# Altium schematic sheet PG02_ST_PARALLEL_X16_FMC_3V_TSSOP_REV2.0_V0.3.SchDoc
size 419 x 241 mm
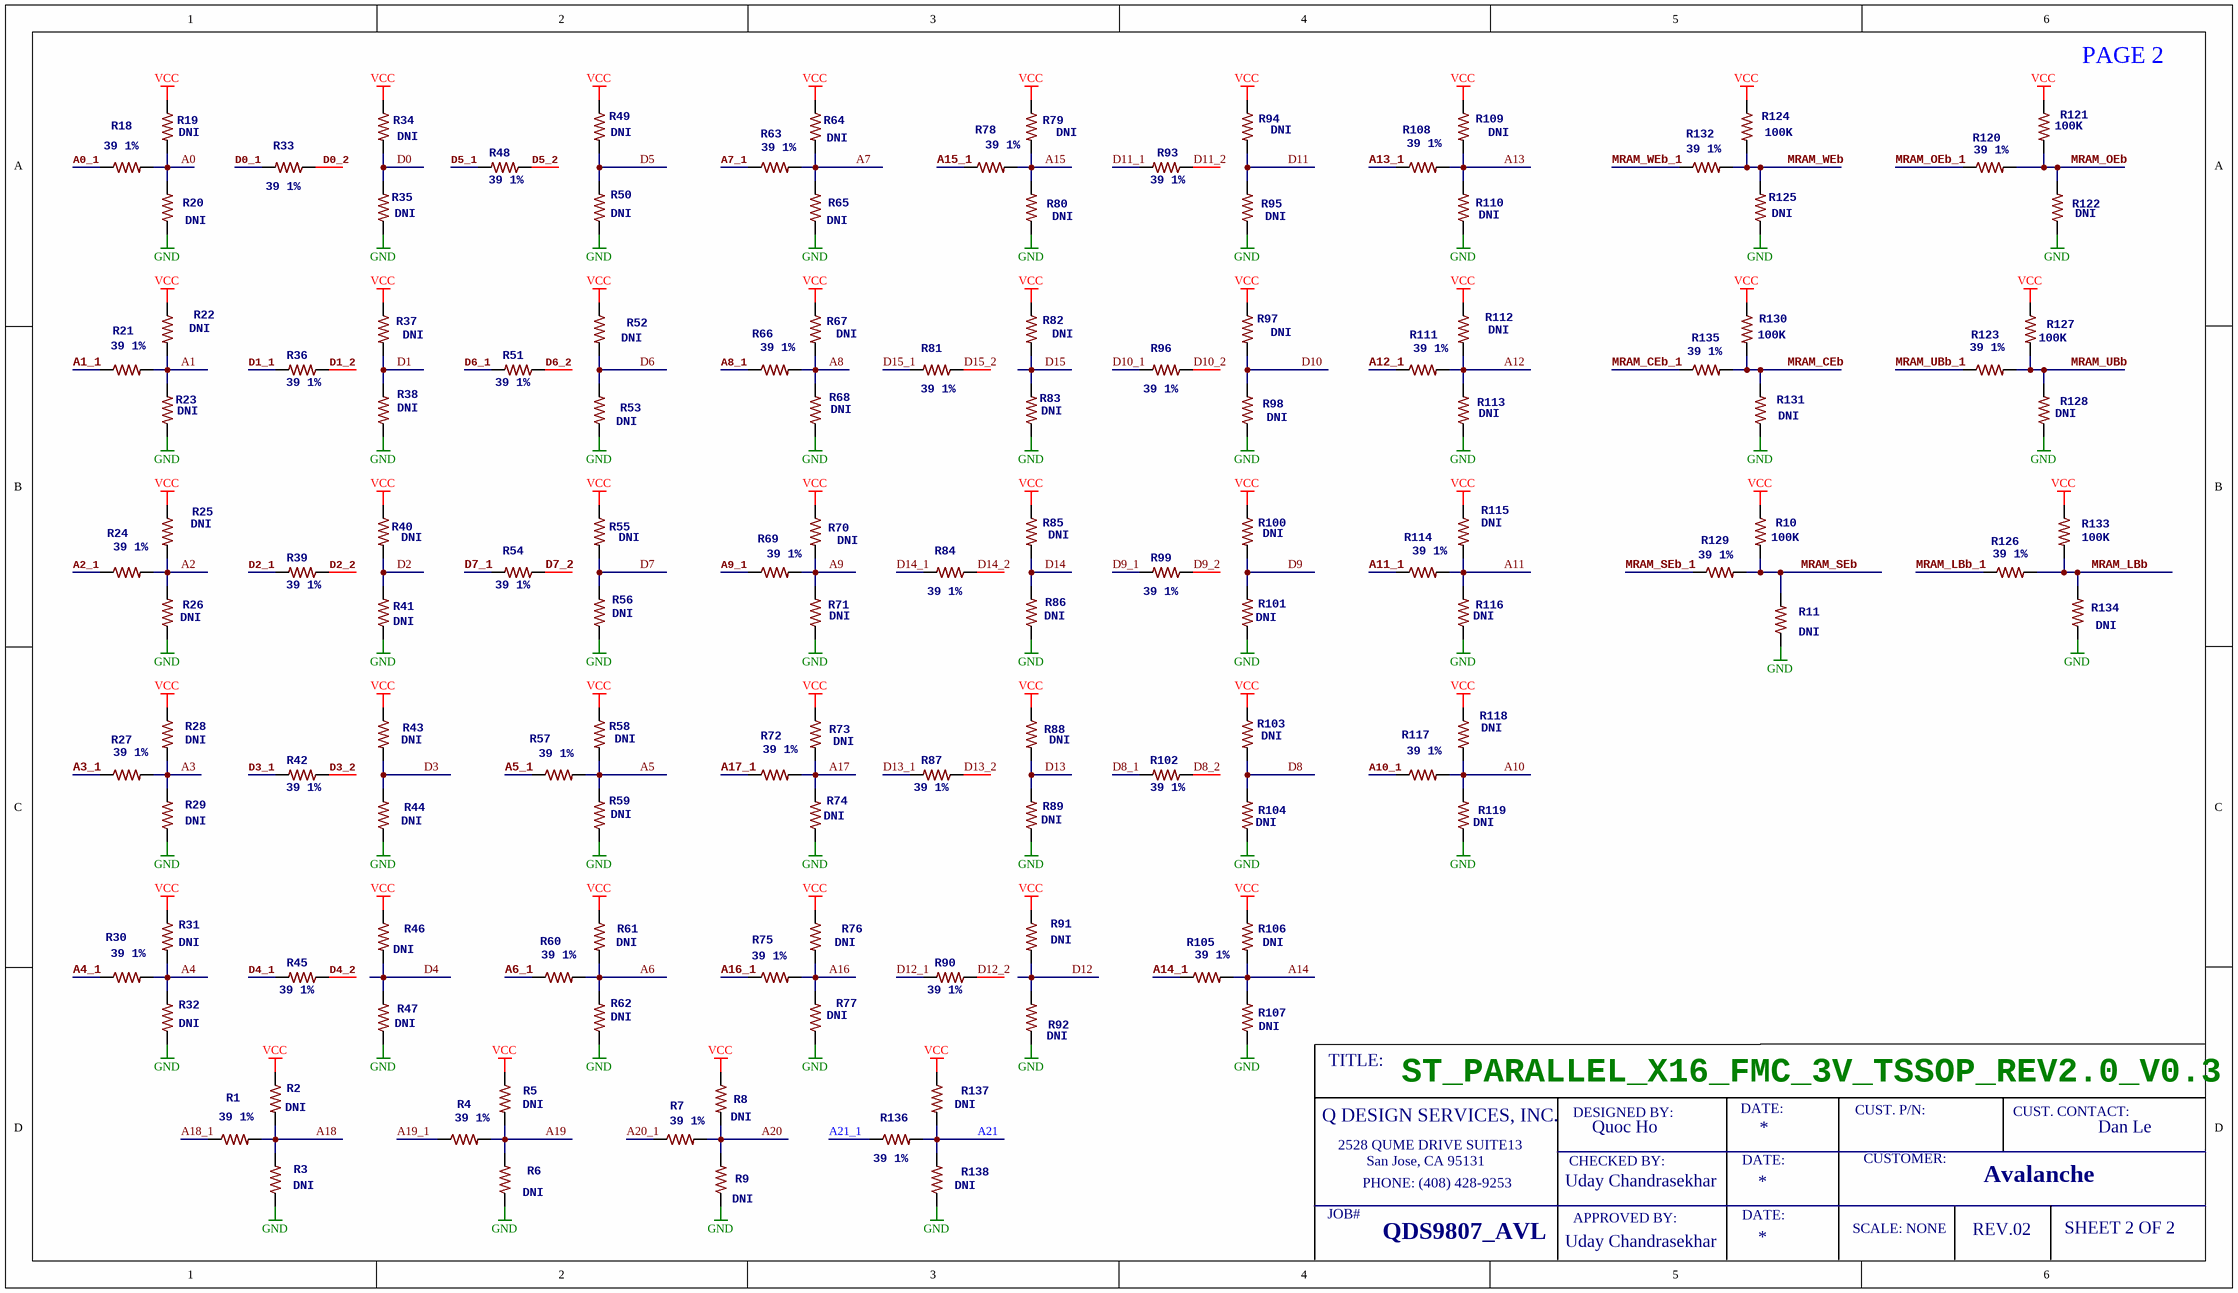
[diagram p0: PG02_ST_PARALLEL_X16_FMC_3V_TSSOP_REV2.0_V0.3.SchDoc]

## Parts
R1  39 1%  [N_0603]
R2  DNI  [N_0402]
R3  DNI  [N_0402]
R4  39 1%  [N_0603]
R5  DNI  [N_0402]
R6  DNI  [N_0402]
R7  39 1%  [N_0603]
R8  DNI  [N_0402]
R9  DNI  [N_0402]
R10  100K  [N_0402]
R11  DNI  [N_0402]
R18  39 1%  [N_0603]
R19  DNI  [N_0402]
R20  DNI  [N_0402]
R21  39 1%  [N_0603]
R22  DNI  [N_0402]
R23  DNI  [N_0402]
R24  39 1%  [N_0603]
R25  DNI  [N_0402]
R26  DNI  [N_0402]
R27  39 1%  [N_0603]
R28  DNI  [N_0402]
R29  DNI  [N_0402]
R30  39 1%  [N_0603]
R31  DNI  [N_0402]
R32  DNI  [N_0402]
R33  39 1%  [N_0603]
R34  DNI  [N_0402]
R35  DNI  [N_0402]
R36  39 1%  [N_0603]
R37  DNI  [N_0402]
R38  DNI  [N_0402]
R39  39 1%  [N_0603]
R40  DNI  [N_0402]
R41  DNI  [N_0402]
R42  39 1%  [N_0603]
R43  DNI  [N_0402]
R44  DNI  [N_0402]
R45  39 1%  [N_0603]
R46  DNI  [N_0402]
R47  DNI  [N_0402]
R48  39 1%  [N_0603]
R49  DNI  [N_0402]
R50  DNI  [N_0402]
R51  39 1%  [N_0603]
R52  DNI  [N_0402]
R53  DNI  [N_0402]
R54  39 1%  [N_0603]
R55  DNI  [N_0402]
R56  DNI  [N_0402]
R57  39 1%  [N_0603]
R58  DNI  [N_0402]
R59  DNI  [N_0402]
R60  39 1%  [N_0603]
R61  DNI  [N_0402]
R62  DNI  [N_0402]
R63  39 1%  [N_0603]
R64  DNI  [N_0402]
R65  DNI  [N_0402]
R66  39 1%  [N_0603]
R67  DNI  [N_0402]
R68  DNI  [N_0402]
R69  39 1%  [N_0603]
R70  DNI  [N_0402]
R71  DNI  [N_0402]
R72  39 1%  [N_0603]
R73  DNI  [N_0402]
R74  DNI  [N_0402]
R75  39 1%  [N_0603]
R76  DNI  [N_0402]
R77  DNI  [N_0402]
R78  39 1%  [N_0603]
R79  DNI  [N_0402]
R80  DNI  [N_0402]
R81  39 1%  [N_0603]
R82  DNI  [N_0402]
R83  DNI  [N_0402]
R84  39 1%  [N_0603]
R85  DNI  [N_0402]
R86  DNI  [N_0402]
R87  39 1%  [N_0603]
R88  DNI  [N_0402]
R89  DNI  [N_0402]
R90  39 1%  [N_0603]
R91  DNI  [N_0402]
R92  DNI  [N_0402]
R93  39 1%  [N_0603]
R94  DNI  [N_0402]
R95  DNI  [N_0402]
R96  39 1%  [N_0603]
R97  DNI  [N_0402]
R98  DNI  [N_0402]
R99  39 1%  [N_0603]
R100  DNI  [N_0402]
R101  DNI  [N_0402]
R102  39 1%  [N_0603]
R103  DNI  [N_0402]
R104  DNI  [N_0402]
R105  39 1%  [N_0603]
R106  DNI  [N_0402]
R107  DNI  [N_0402]
R108  39 1%  [N_0603]
R109  DNI  [N_0402]
R110  DNI  [N_0402]
R111  39 1%  [N_0603]
R112  DNI  [N_0402]
R113  DNI  [N_0402]
R114  39 1%  [N_0603]
R115  DNI  [N_0402]
R116  DNI  [N_0402]
R117  39 1%  [N_0603]
R118  DNI  [N_0402]
R119  DNI  [N_0402]
R120  39 1%  [N_0603]
R121  100K  [N_0402]
R122  DNI  [N_0402]
R123  39 1%  [N_0603]
R124  100K  [N_0402]
R125  DNI  [N_0402]
R126  39 1%  [N_0603]
R127  100K  [N_0402]
R128  DNI  [N_0402]
R129  39 1%  [N_0603]
R130  100K  [N_0402]
R131  DNI  [N_0402]
R132  39 1%  [N_0603]
R133  100K  [N_0402]
R134  DNI  [N_0402]
R135  39 1%  [N_0603]
R136  39 1%  [N_0603]
R137  DNI  [N_0402]
R138  DNI  [N_0402]

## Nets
GND: R3.1 R6.1 R9.1 R11.1 R20.1 R23.1 R26.1 R29.1 R32.1 R35.1 R38.1 R41.1 R44.1 R47.1 R50.1 R53.1 R56.1 R59.1 R62.1 R65.1 R68.1 R71.1 R74.1 R77.1 R80.1 R83.1 R86.1 R89.1 R92.1 R95.1 R98.1 R101.1 R104.1 R107.1 R110.1 R113.1 R116.1 R119.1 R122.1 R125.1 R128.1 R131.1 R134.1 R138.1
VCC: R2.1 R5.1 R8.1 R10.1 R19.1 R22.1 R25.1 R28.1 R31.1 R34.1 R37.1 R40.1 R43.1 R46.1 R49.1 R52.1 R55.1 R58.1 R61.1 R64.1 R67.1 R70.1 R73.1 R76.1 R79.1 R82.1 R85.1 R88.1 R91.1 R94.1 R97.1 R100.1 R103.1 R106.1 R109.1 R112.1 R115.1 R118.1 R121.1 R124.1 R127.1 R130.1 R133.1 R137.1
A0: R18.2 R19.2 R20.2
A0_1: R18.1
A1: R21.1 R22.2 R23.2
A1_1: R21.2
A2: R24.1 R25.2 R26.2
A2_1: R24.2
A3: R27.1 R28.2 R29.2
A3_1: R27.2
A4: R30.1 R31.2 R32.2
A4_1: R30.2
A5: R57.1 R58.2 R59.2
A5_1: R57.2
A6: R60.1 R61.2 R62.2
A6_1: R60.2
A7: R63.1 R64.2 R65.2
A7_1: R63.2
A8: R66.1 R67.2 R68.2
A8_1: R66.2
A9: R69.1 R70.2 R71.2
A9_1: R69.2
A10: R117.1 R118.2 R119.2
A10_1: R117.2
A11: R114.1 R115.2 R116.2
A11_1: R114.2
A12: R111.1 R112.2 R113.2
A12_1: R111.2
A13: R108.1 R109.2 R110.2
A13_1: R108.2
A14: R105.1 R106.2 R107.2
A14_1: R105.2
A15: R78.1 R79.2 R80.2
A15_1: R78.2
A16: R75.1 R76.2 R77.2
A16_1: R75.2
A17: R72.1 R73.2 R74.2
A17_1: R72.2
A18: R1.1 R2.2 R3.2
A18_1: R1.2
A19: R4.1 R5.2 R6.2
A19_1: R4.2
A20: R7.1 R8.2 R9.2
A20_1: R7.2
A21: R136.1 R137.2 R138.2
A21_1: R136.2
D0: R34.2 R35.2
D0_1: R33.1
D0_2: R33.2
D1: R37.2 R38.2
D1_1: R36.1
D1_2: R36.2
D2: R40.2 R41.2
D2_1: R39.1
D2_2: R39.2
D3: R43.2 R44.2
D3_1: R42.2
D3_2: R42.1
D4: R46.2 R47.2
D4_1: R45.1
D4_2: R45.2
D5: R49.2 R50.2
D5_1: R48.1
D5_2: R48.2
D6: R52.2 R53.2
D6_1: R51.1
D6_2: R51.2
D7: R55.2 R56.2
D7_1: R54.1
D7_2: R54.2
D8: R103.2 R104.2
D8_1: R102.1
D8_2: R102.2
D9: R100.2 R101.2
D9_1: R99.1
D9_2: R99.2
D10: R97.2 R98.2
D10_1: R96.1
D10_2: R96.2
D11: R94.2 R95.2
D11_1: R93.1
D11_2: R93.2
D12: R91.2 R92.2
D12_1: R90.1
D12_2: R90.2
D13: R88.2 R89.2
D13_1: R87.1
D13_2: R87.2
D14: R85.2 R86.2
D14_1: R84.1
D14_2: R84.2
D15: R82.2 R83.2
D15_1: R81.1
D15_2: R81.2
MRAM_CEb: R130.2 R131.2 R135.1
MRAM_CEb_1: R135.2
MRAM_LBb: R126.1 R133.2 R134.2
MRAM_LBb_1: R126.2
MRAM_OEb: R120.1 R121.2 R122.2
MRAM_OEb_1: R120.2
MRAM_SEb: R10.2 R11.2 R129.1
MRAM_SEb_1: R129.2
MRAM_UBb: R123.1 R127.2 R128.2
MRAM_UBb_1: R123.2
MRAM_WEb: R124.2 R125.2 R132.1
MRAM_WEb_1: R132.2

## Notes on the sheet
- PAGE 2
- TITLE:
- ST_PARALLEL_X16_FMC_3V_TSSOP_REV2.0_V0.3
- DATE:
- Q DESIGN SERVICES, INC.
- 2528 QUME DRIVE SUITE13
- San Jose, CA 95131
- CHECKED BY:
- DESIGNED BY:
- Quoc Ho
- CUST. P/N:
- CUSTOMER:
- CUST. CONTACT:
- Dan Le
- JOB#
- PHONE: (408) 428-9253
- QDS9807_AVL
- Uday Chandrasekhar
- APPROVED BY:
- SCALE: NONE
- REV.02
- Avalanche
- SHEET 2 OF 2

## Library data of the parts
R1 R4 R7 R18 R21 R24 R27 R30 R33 R36 R39 R42 R45 R48 R51 R54 R57 R60 R63 R66 R69 R72 R75 R78 R81 R84 R87 R90 R93 R96 R99 R102 R105 R108 R111 R114 R117 R120 R123 R126 R132 R135 R136 = R-US_R0603: RES SMD 39 OHM 1% 1/16W 0402; Part No.: RC0402FR-0739RL
R2 R3 R5 R6 R8 R9 R11 R19 R20 R22 R23 R25 R26 R28 R29 R31 R32 R34 R35 R37 R38 R40 R41 R43 R44 R46 R47 R49 R50 R52 R53 R55 R56 R58 R59 R61 R62 R64 R65 R67 R68 R70 R71 R73 R74 R76 R77 R79 R80 R82 R83 R85 R86 R88 R89 R91 R92 R94 R95 R97 R98 R100 R101 R103 R104 R106 R107 R109 R110 R112 R113 R115 R116 R118 R119 R122 R125 R128 R131 R134 R137 = R-US_R0603
R10 = R-US_R0603: RES SMD 100K OHM 1% 1/10W 0402
R121 R124 R127 R130 R133 = R-US_R0603: RES SMD 100K OHM 1% 1/10W 0402; Part No.: ERJ-2RKF1003X
R129 = R-US_R0603: RES SMD 39 OHM 1% 1/16W 0402
R138 = R-US_R0603: Part Number: ERJ-1GNF91R0C; Value: 91(DNI)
